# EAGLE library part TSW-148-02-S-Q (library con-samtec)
THROUGH-HOLE .025" SQ POST HEADER Source: Samtec TSW.pdf
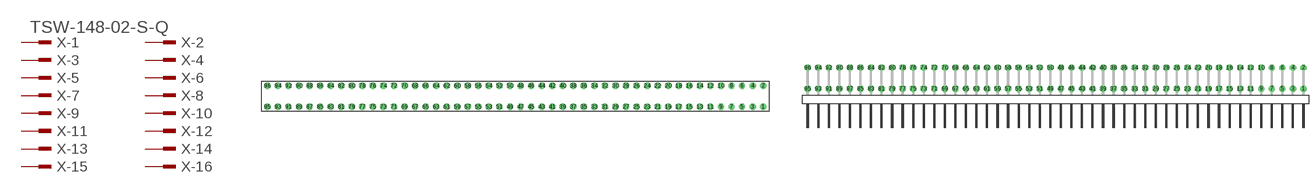
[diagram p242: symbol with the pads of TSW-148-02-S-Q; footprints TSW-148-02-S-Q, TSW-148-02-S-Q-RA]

Designator prefix X; gates -1=MPINV -2=MPIN -3=MPIN -4=MPIN -5=MPIN -6=MPIN -7=MPIN -8=MPIN -9=MPIN -10=MPIN -11=MPIN -12=MPIN -13=MPIN -14=MPIN -15=MPIN -16=MPIN -17=MPIN -18=MPIN -19=MPIN -20=MPIN -21=MPIN -22=MPIN -23=MPIN -24=MPIN -25=MPIN -26=MPIN -27=MPIN -28=MPIN -29=MPIN -30=MPIN -31=MPIN -32=MPIN -33=MPIN -34=MPIN -35=MPIN -36=MPIN -37=MPIN -38=MPIN -39=MPIN -40=MPIN -41=MPIN -42=MPIN -43=MPIN -44=MPIN -45=MPIN -46=MPIN -47=MPIN -48=MPIN -49=MPIN -50=MPIN -51=MPIN -52=MPIN -53=MPIN -54=MPIN -55=MPIN -56=MPIN -57=MPIN -58=MPIN -59=MPIN -60=MPIN -61=MPIN -62=MPIN -63=MPIN -64=MPIN -65=MPIN -66=MPIN -67=MPIN -68=MPIN -69=MPIN -70=MPIN -71=MPIN -72=MPIN -73=MPIN -74=MPIN -75=MPIN -76=MPIN -77=MPIN -78=MPIN -79=MPIN -80=MPIN -81=MPIN -82=MPIN -83=MPIN -84=MPIN -85=MPIN -86=MPIN -87=MPIN -88=MPIN -89=MPIN -90=MPIN -91=MPIN -92=MPIN -93=MPIN -94=MPIN -95=MPIN -96=MPIN

## TSW-148-02-S-Q (OC_FARNELL: unknown; OC_NEWARK: unknown)  [TSW-148-02-S-Q]
1  -1:1  pas
2  -2:1  pas
3  -3:1  pas
4  -4:1  pas
5  -5:1  pas
6  -6:1  pas
7  -7:1  pas
8  -8:1  pas
9  -9:1  pas
10  -10:1  pas
11  -11:1  pas
12  -12:1  pas
13  -13:1  pas
14  -14:1  pas
15  -15:1  pas
16  -16:1  pas
17  -17:1  pas
18  -18:1  pas
19  -19:1  pas
20  -20:1  pas
21  -21:1  pas
22  -22:1  pas
23  -23:1  pas
24  -24:1  pas
25  -25:1  pas
26  -26:1  pas
27  -27:1  pas
28  -28:1  pas
29  -29:1  pas
30  -30:1  pas
31  -31:1  pas
32  -32:1  pas
33  -33:1  pas
34  -34:1  pas
35  -35:1  pas
36  -36:1  pas
37  -37:1  pas
38  -38:1  pas
39  -39:1  pas
40  -40:1  pas
41  -41:1  pas
42  -42:1  pas
43  -43:1  pas
44  -44:1  pas
45  -45:1  pas
46  -46:1  pas
47  -47:1  pas
48  -48:1  pas
49  -49:1  pas
50  -50:1  pas
51  -51:1  pas
52  -52:1  pas
53  -53:1  pas
54  -54:1  pas
55  -55:1  pas
56  -56:1  pas
57  -57:1  pas
58  -58:1  pas
59  -59:1  pas
60  -60:1  pas
61  -61:1  pas
62  -62:1  pas
63  -63:1  pas
64  -64:1  pas
65  -65:1  pas
66  -66:1  pas
67  -67:1  pas
68  -68:1  pas
69  -69:1  pas
70  -70:1  pas
71  -71:1  pas
72  -72:1  pas
73  -73:1  pas
74  -74:1  pas
75  -75:1  pas
76  -76:1  pas
77  -77:1  pas
78  -78:1  pas
79  -79:1  pas
80  -80:1  pas
81  -81:1  pas
82  -82:1  pas
83  -83:1  pas
84  -84:1  pas
85  -85:1  pas
86  -86:1  pas
87  -87:1  pas
88  -88:1  pas
89  -89:1  pas
90  -90:1  pas
91  -91:1  pas
92  -92:1  pas
93  -93:1  pas
94  -94:1  pas
95  -95:1  pas
96  -96:1  pas

## TSW-148-02-S-Q-RA (OC_FARNELL: unknown; OC_NEWARK: unknown)  [TSW-148-02-S-Q-RA]
Pads as for TSW-148-02-S-Q

## Footprint TSW-148-02-S-Q (pad centres in mm)
THROUGH-HOLE .025" SQ POST HEADER Source: Samtec TSW.pdf
drill 1 pad 1.5 octagon: 1 59.69,-2.54; 2 59.69,2.54; 3 57.15,-2.54; 4 57.15,2.54; 5 54.61,-2.54; 6 54.61,2.54; 7 52.07,-2.54; 8 52.07,2.54; 9 49.53,-2.54; 10 49.53,2.54; 11 46.99,-2.54; 12 46.99,2.54; 13 44.45,-2.54; 14 44.45,2.54; 15 41.91,-2.54; 16 41.91,2.54; 17 39.37,-2.54; 18 39.37,2.54; 19 36.83,-2.54; 20 36.83,2.54; 21 34.29,-2.54; 22 34.29,2.54; 23 31.75,-2.54; 24 31.75,2.54; 25 29.21,-2.54; 26 29.21,2.54; 27 26.67,-2.54; 28 26.67,2.54; 29 24.13,-2.54; 30 24.13,2.54; 31 21.59,-2.54; 32 21.59,2.54; 33 19.05,-2.54; 34 19.05,2.54; 35 16.51,-2.54; 36 16.51,2.54; 37 13.97,-2.54; 38 13.97,2.54; 39 11.43,-2.54; 40 11.43,2.54; 41 8.89,-2.54; 42 8.89,2.54; 43 6.35,-2.54; 44 6.35,2.54; 45 3.81,-2.54; 46 3.81,2.54; 47 1.27,-2.54; 48 1.27,2.54; 49 -1.27,-2.54; 50 -1.27,2.54; 51 -3.81,-2.54; 52 -3.81,2.54; 53 -6.35,-2.54; 54 -6.35,2.54; 55 -8.89,-2.54; 56 -8.89,2.54; 57 -11.43,-2.54; 58 -11.43,2.54; 59 -13.97,-2.54; 60 -13.97,2.54; 61 -16.51,-2.54; 62 -16.51,2.54; 63 -19.05,-2.54; 64 -19.05,2.54; 65 -21.59,-2.54; 66 -21.59,2.54; 67 -24.13,-2.54; 68 -24.13,2.54; 69 -26.67,-2.54; 70 -26.67,2.54; 71 -29.21,-2.54; 72 -29.21,2.54; 73 -31.75,-2.54; 74 -31.75,2.54; 75 -34.29,-2.54; 76 -34.29,2.54; 77 -36.83,-2.54; 78 -36.83,2.54; 79 -39.37,-2.54; 80 -39.37,2.54; 81 -41.91,-2.54; 82 -41.91,2.54; 83 -44.45,-2.54; 84 -44.45,2.54; 85 -46.99,-2.54; 86 -46.99,2.54; 87 -49.53,-2.54; 88 -49.53,2.54; 89 -52.07,-2.54; 90 -52.07,2.54; 91 -54.61,-2.54; 92 -54.61,2.54; 93 -57.15,-2.54; 94 -57.15,2.54; 95 -59.69,-2.54; 96 -59.69,2.54

## Footprint TSW-148-02-S-Q-RA (pad centres in mm)
THROUGH-HOLE .025" SQ POST HEADER Source: Samtec TSW.pdf
drill 1 pad 1.5 octagon: 1 59.69,1.524; 2 59.69,6.604; 3 57.15,1.524; 4 57.15,6.604; 5 54.61,1.524; 6 54.61,6.604; 7 52.07,1.524; 8 52.07,6.604; 9 49.53,1.524; 10 49.53,6.604; 11 46.99,1.524; 12 46.99,6.604; 13 44.45,1.524; 14 44.45,6.604; 15 41.91,1.524; 16 41.91,6.604; 17 39.37,1.524; 18 39.37,6.604; 19 36.83,1.524; 20 36.83,6.604; 21 34.29,1.524; 22 34.29,6.604; 23 31.75,1.524; 24 31.75,6.604; 25 29.21,1.524; 26 29.21,6.604; 27 26.67,1.524; 28 26.67,6.604; 29 24.13,1.524; 30 24.13,6.604; 31 21.59,1.524; 32 21.59,6.604; 33 19.05,1.524; 34 19.05,6.604; 35 16.51,1.524; 36 16.51,6.604; 37 13.97,1.524; 38 13.97,6.604; 39 11.43,1.524; 40 11.43,6.604; 41 8.89,1.524; 42 8.89,6.604; 43 6.35,1.524; 44 6.35,6.604; 45 3.81,1.524; 46 3.81,6.604; 47 1.27,1.524; 48 1.27,6.604; 49 -1.27,1.524; 50 -1.27,6.604; 51 -3.81,1.524; 52 -3.81,6.604; 53 -6.35,1.524; 54 -6.35,6.604; 55 -8.89,1.524; 56 -8.89,6.604; 57 -11.43,1.524; 58 -11.43,6.604; 59 -13.97,1.524; 60 -13.97,6.604; 61 -16.51,1.524; 62 -16.51,6.604; 63 -19.05,1.524; 64 -19.05,6.604; 65 -21.59,1.524; 66 -21.59,6.604; 67 -24.13,1.524; 68 -24.13,6.604; 69 -26.67,1.524; 70 -26.67,6.604; 71 -29.21,1.524; 72 -29.21,6.604; 73 -31.75,1.524; 74 -31.75,6.604; 75 -34.29,1.524; 76 -34.29,6.604; 77 -36.83,1.524; 78 -36.83,6.604; 79 -39.37,1.524; 80 -39.37,6.604; 81 -41.91,1.524; 82 -41.91,6.604; 83 -44.45,1.524; 84 -44.45,6.604; 85 -46.99,1.524; 86 -46.99,6.604; 87 -49.53,1.524; 88 -49.53,6.604; 89 -52.07,1.524; 90 -52.07,6.604; 91 -54.61,1.524; 92 -54.61,6.604; 93 -57.15,1.524; 94 -57.15,6.604; 95 -59.69,1.524; 96 -59.69,6.604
